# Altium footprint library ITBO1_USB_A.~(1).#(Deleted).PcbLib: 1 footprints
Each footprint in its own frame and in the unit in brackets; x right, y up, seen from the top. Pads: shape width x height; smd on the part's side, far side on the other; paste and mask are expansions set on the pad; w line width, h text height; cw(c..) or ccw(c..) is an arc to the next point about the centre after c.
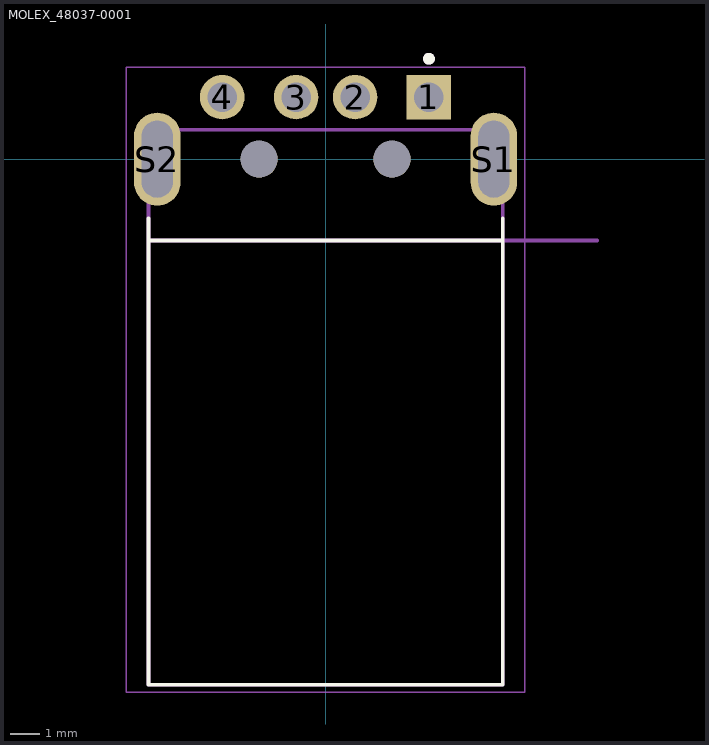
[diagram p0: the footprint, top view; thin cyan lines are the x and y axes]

## MOLEX_48037-0001 [mm]
pads (8):
  rect 1.508x1.508 hole 1: 1(3.5,2.1)
  round 1.508 hole 1: 2(1,2.1) 3(-1,2.1) 4(-3.5,2.1)
  oval 1.575x3.15 hole 1.05 slot 2.6 at 90 deg: S1(5.7,0) S2(-5.7,0)
  round 1.25 hole 1.25 unplated: ""(-2.25,0) ""(2.25,0)
Top Overlay:
  circle w0.2: c3.5,3.4 r0.1
  lines w0.127: -6,-2 -6,-2.75 ; 6,-2 6,-2.75 ; -6,-2.75 -6,-17.8 6,-17.8 6,-2.75 ; -6,-2.75 6,-2.75
Mechanical 13:
  circle w0.2: c3.5,3.4 r0.1
  lines w0.127: 9.2,-2.75 6,-2.75 ; -6,-2.75 -6,-17.8 6,-17.8 6,-2.75 ; -6,-2.75 6,-2.75 ; -6,-2.75 -6,1 6,1 6,-2.75
  text "PCB EDGE" at 6.28,-2.47 h0.41
Mechanical 15:
  lines w0.05: -6.75,-18.05 6.75,-18.05 6.75,3.11 -6.75,3.11 -6.75,-18.05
